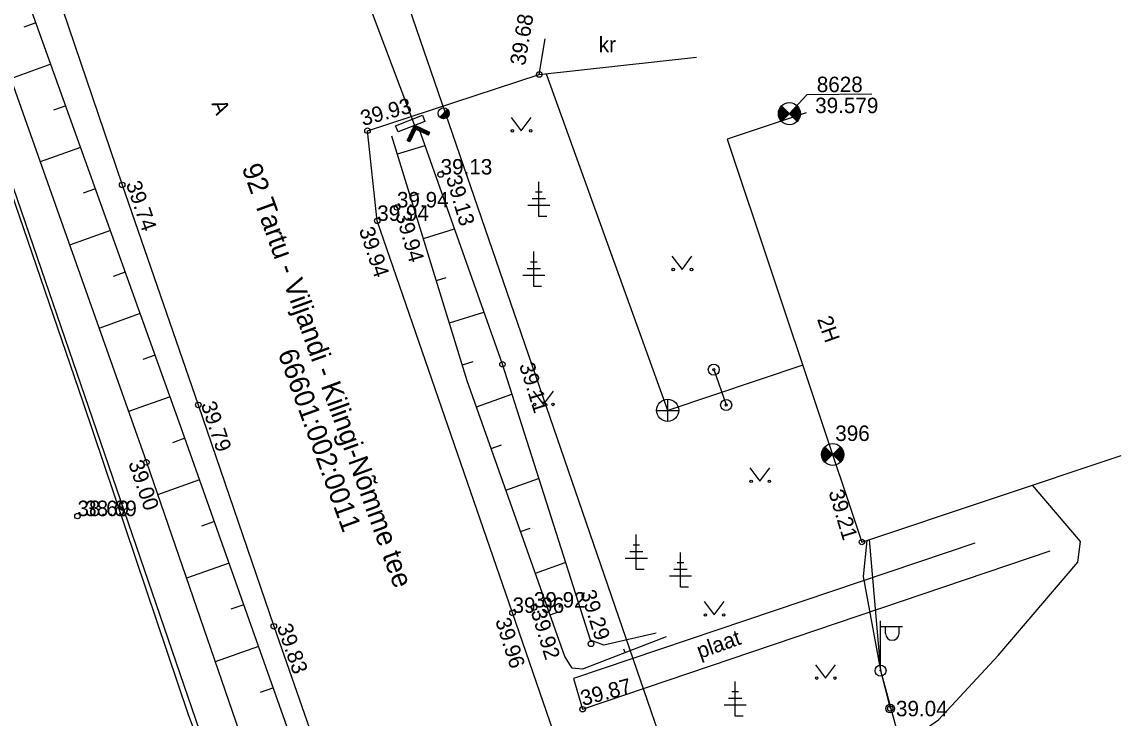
# Model space of a CAD drawing. Extents: x 627548 to 628052, y 6467984 to 6468802.
# Drawn here: x 627961.02 to 628010.83, y 6468057.42 to 6468088.95 of the extents above; entities that cross this region are included whole.
import ezdxf

# ---------------------------------------------------------------- set-up
doc = ezdxf.new("R2010")
doc.units = 0
for name, color, linetype in [('ALUSVORK', 7, 'Continuous'), ('HALJASTUS', 7, 'Continuous'), ('HOONE', 7, 'Continuous'), ('KKAEV', 7, 'Continuous'), ('KORGUS-EH2000', 7, 'Continuous'), ('KTRASS', 7, 'Continuous'), ('LIIKLUS', 7, 'Continuous'), ('MOOTKORG-EH2000', 7, 'Continuous'), ('MOOTMPUNKT', 7, 'Continuous'), ('MPKAABEL', 7, 'Continuous'), ('MPOHULIIN', 7, 'Continuous'), ('PIIR', 7, 'Continuous'), ('POST', 7, 'Continuous'), ('PUU', 7, 'Continuous'), ('RELJEEF', 7, 'Continuous'), ('SITRASS', 7, 'Continuous'), ('TEE', 7, 'Continuous'), ('TRUUP', 7, 'Continuous')]:
    doc.layers.add(name, color=color, linetype=linetype)

msp = doc.modelspace()

# ---------------------------------------------------------------- linework, layer by layer
at = {"layer": 'ALUSVORK'}
for p, q in [((627995.446, 6468085.154), (627996.154, 6468084.446)), ((627995.446, 6468084.446), (627996.154, 6468085.154)), ((627995.446, 6468085.154), (627995.446, 6468085.154)), ((627995.446, 6468085.154), (627995.446, 6468085.154)), ((627996.154, 6468085.154), (627996.154, 6468085.154)), ((627995.446, 6468084.446), (627995.446, 6468084.446)), ((627996.154, 6468084.446), (627996.154, 6468084.446)), ((627996.154, 6468084.446), (627996.154, 6468084.446)), ((627997.404, 6468069.713), (627998.111, 6468069.006)), ((627997.404, 6468069.006), (627998.111, 6468069.713)), ((627997.404, 6468069.713), (627997.404, 6468069.713)), ((627997.404, 6468069.713), (627997.404, 6468069.713)), ((627998.111, 6468069.713), (627998.111, 6468069.713)), ((627997.404, 6468069.006), (627997.404, 6468069.006)), ((627998.111, 6468069.006), (627998.111, 6468069.006)), ((627998.111, 6468069.006), (627998.111, 6468069.006))]:
    msp.add_line(p, q, dxfattribs=at)
msp.add_lwpolyline([(627999.534, 6468085.677), (627996.592, 6468085.654), (627995.8, 6468084.8)], dxfattribs=at)
for centre in [(627995.8, 6468084.8), (627997.757, 6468069.359)]:
    msp.add_circle(centre, 0.5, dxfattribs=at)
for centre, radius, start, end in [((627995.8, 6468084.8), 0.475, 135.0005, 224.9995), ((627995.8, 6468084.8), 0.45, 135.0005, 224.9995), ((627995.8, 6468084.8), 0.425, 135.0005, 224.9995), ((627995.8, 6468084.8), 0.4, 135.0005, 224.9995), ((627995.8, 6468084.8), 0.375, 135.0005, 224.9995), ((627995.8, 6468084.8), 0.35, 135.0005, 224.9995), ((627995.8, 6468084.8), 0.325, 135.0005, 224.9995), ((627995.8, 6468084.8), 0.3, 135.0005, 224.9995), ((627995.8, 6468084.8), 0.275, 135.0005, 224.9995), ((627995.8, 6468084.8), 0.275, 315.0005, 44.9995), ((627995.8, 6468084.8), 0.3, 315.0005, 44.9995), ((627995.8, 6468084.8), 0.325, 315.0005, 44.9995), ((627995.8, 6468084.8), 0.35, 315.0005, 44.9995), ((627995.8, 6468084.8), 0.375, 315.0005, 44.9995), ((627995.8, 6468084.8), 0.4, 315.0005, 44.9995), ((627995.8, 6468084.8), 0.425, 315.0005, 44.9995), ((627995.8, 6468084.8), 0.45, 315.0005, 44.9995), ((627995.8, 6468084.8), 0.475, 315.0005, 44.9995), ((627995.8, 6468084.8), 0.25, 135.0005, 224.9995), ((627995.8, 6468084.8), 0.225, 135.0005, 224.9995), ((627995.8, 6468084.8), 0.2, 135.0005, 224.9995), ((627995.8, 6468084.8), 0.175, 135.0005, 224.9995), ((627995.8, 6468084.8), 0.15, 135.0005, 224.9995), ((627995.8, 6468084.8), 0.125, 135.0005, 224.9995), ((627995.8, 6468084.8), 0.1, 135.0005, 224.9995), ((627995.8, 6468084.8), 0.075, 135.0005, 224.9995), ((627995.8, 6468084.8), 0.05, 135.0005, 224.9995), ((627995.8, 6468084.8), 0.025, 135.0005, 224.9995), ((627995.8, 6468084.8), 0.025, 315.0005, 44.9995), ((627995.8, 6468084.8), 0.05, 315.0005, 44.9995), ((627995.8, 6468084.8), 0.075, 315.0005, 44.9995), ((627995.8, 6468084.8), 0.1, 315.0005, 44.9995), ((627995.8, 6468084.8), 0.125, 315.0005, 44.9995), ((627995.8, 6468084.8), 0.15, 315.0005, 44.9995), ((627995.8, 6468084.8), 0.175, 315.0005, 44.9995), ((627995.8, 6468084.8), 0.2, 315.0005, 44.9995), ((627995.8, 6468084.8), 0.225, 315.0005, 44.9995), ((627995.8, 6468084.8), 0.25, 315.0005, 44.9995), ((627997.757, 6468069.359), 0.475, 135.0005, 224.9995), ((627997.757, 6468069.359), 0.45, 135.0005, 224.9995), ((627997.757, 6468069.359), 0.425, 135.0005, 224.9995), ((627997.757, 6468069.359), 0.4, 135.0005, 224.9995), ((627997.757, 6468069.359), 0.375, 135.0005, 224.9995), ((627997.757, 6468069.359), 0.35, 135.0005, 224.9995), ((627997.757, 6468069.359), 0.325, 135.0005, 224.9995), ((627997.757, 6468069.359), 0.3, 135.0005, 224.9995), ((627997.757, 6468069.359), 0.275, 135.0005, 224.9995), ((627997.757, 6468069.359), 0.275, 315.0005, 44.9995), ((627997.757, 6468069.359), 0.3, 315.0005, 44.9995), ((627997.757, 6468069.359), 0.325, 315.0005, 44.9995), ((627997.757, 6468069.359), 0.35, 315.0005, 44.9995), ((627997.757, 6468069.359), 0.375, 315.0005, 44.9995), ((627997.757, 6468069.359), 0.4, 315.0005, 44.9995), ((627997.757, 6468069.359), 0.425, 315.0005, 44.9995), ((627997.757, 6468069.359), 0.45, 315.0005, 44.9995), ((627997.757, 6468069.359), 0.475, 315.0005, 44.9995), ((627997.757, 6468069.359), 0.25, 135.0005, 224.9995), ((627997.757, 6468069.359), 0.225, 135.0005, 224.9995), ((627997.757, 6468069.359), 0.2, 135.0005, 224.9995), ((627997.757, 6468069.359), 0.175, 135.0005, 224.9995), ((627997.757, 6468069.359), 0.15, 135.0005, 224.9995), ((627997.757, 6468069.359), 0.125, 135.0005, 224.9995), ((627997.757, 6468069.359), 0.1, 135.0005, 224.9995), ((627997.757, 6468069.359), 0.075, 135.0005, 224.9995), ((627997.757, 6468069.359), 0.05, 135.0005, 224.9995), ((627997.757, 6468069.359), 0.025, 135.0005, 224.9995), ((627997.757, 6468069.359), 0.025, 315.0005, 44.9995), ((627997.757, 6468069.359), 0.05, 315.0005, 44.9995), ((627997.757, 6468069.359), 0.075, 315.0005, 44.9995), ((627997.757, 6468069.359), 0.1, 315.0005, 44.9995), ((627997.757, 6468069.359), 0.125, 315.0005, 44.9995), ((627997.757, 6468069.359), 0.15, 315.0005, 44.9995), ((627997.757, 6468069.359), 0.175, 315.0005, 44.9995), ((627997.757, 6468069.359), 0.2, 315.0005, 44.9995), ((627997.757, 6468069.359), 0.225, 315.0005, 44.9995), ((627997.757, 6468069.359), 0.25, 315.0005, 44.9995)]:
    msp.add_arc(centre, radius, start, end, dxfattribs=at)
at = {"layer": 'HALJASTUS'}
for p, q in [((627983.182, 6468084.628), (627983.645, 6468084.021)), ((627983.645, 6468084.021), (627984.091, 6468084.628)), ((627990.47, 6468078.346), (627990.933, 6468077.739)), ((627990.933, 6468077.739), (627991.379, 6468078.346)), ((627984.191, 6468072.231), (627984.655, 6468071.625)), ((627984.655, 6468071.625), (627985.1, 6468072.231)), ((627994.002, 6468068.754), (627994.465, 6468068.147)), ((627994.465, 6468068.147), (627994.911, 6468068.754)), ((627991.928, 6468062.696), (627992.391, 6468062.089)), ((627992.391, 6468062.089), (627992.837, 6468062.696)), ((627996.973, 6468059.835), (627997.437, 6468059.228)), ((627997.437, 6468059.228), (627997.882, 6468059.835))]:
    msp.add_line(p, q, dxfattribs=at)
for centre in [(627983.244, 6468084.021), (627984.073, 6468084.021), (627990.532, 6468077.739), (627991.361, 6468077.739), (627984.254, 6468071.625), (627985.082, 6468071.625), (627994.064, 6468068.147), (627994.893, 6468068.147), (627991.99, 6468062.089), (627992.819, 6468062.089), (627997.036, 6468059.228), (627997.864, 6468059.228)]:
    msp.add_circle(centre, 0.055, dxfattribs=at)
at = {"layer": 'HOONE'}
msp.add_lwpolyline([(627996.552, 6468084.834), (627992.984, 6468083.642), (627999.083, 6468065.393), (628010.826, 6468069.318)], dxfattribs=at)
at = {"layer": 'KKAEV'}
for p, q in [((627990.282, 6468070.859), (627990.282, 6468071.859)), ((627989.782, 6468071.359), (627990.782, 6468071.359))]:
    msp.add_line(p, q, dxfattribs=at)
msp.add_circle((627990.282, 6468071.359), 0.5, dxfattribs=at)
at = {"layer": 'KORGUS-EH2000'}
for centre in [(627984.465, 6468086.573), (627976.679, 6468084.026), (627965.56, 6468081.571), (627982.794, 6468073.444), (627969.012, 6468071.605), (627966.658, 6468069.004), (627999.083, 6468065.393), (627972.432, 6468061.577), (627986.81, 6468060.78), (627986.425, 6468057.82), (628000.367, 6468057.85)]:
    msp.add_circle(centre, 0.125, dxfattribs=at)
at = {"layer": 'KTRASS'}
for points in [[(627990.282, 6468071.359), (627984.783, 6468086.585)], [(627996.405, 6468073.406), (627990.282, 6468071.359)]]:
    msp.add_lwpolyline(points, dxfattribs=at)
at = {"layer": 'LIIKLUS'}
msp.add_lwpolyline([(627992.371, 6468073.203), (627992.932, 6468071.603)], dxfattribs=at)
for centre, radius in [((627992.371, 6468073.203), 0.25), ((627992.371, 6468073.203), 0.05), ((627992.932, 6468071.603), 0.25), ((627992.932, 6468071.603), 0.05)]:
    msp.add_circle(centre, radius, dxfattribs=at)
at = {"layer": 'MOOTMPUNKT'}
for centre in [(627979.991, 6468082.043), (627978.012, 6468080.551), (627977.119, 6468079.943), (627963.533, 6468066.568), (627983.251, 6468062.182), (627984.22, 6468062.427)]:
    msp.add_circle(centre, 0.125, dxfattribs=at)
at = {"layer": 'MPKAABEL'}
msp.add_lwpolyline([(627999.313, 6468065.47), (627999.141, 6468063.833), (627999.927, 6468059.569)], dxfattribs=at)
at = {"layer": 'MPOHULIIN'}
for points in [[(627999.41, 6468065.503), (627999.927, 6468059.569)], [(627999.927, 6468059.569), (628001.908, 6468052.307)]]:
    msp.add_lwpolyline(points, dxfattribs=at)
at = {"layer": 'PIIR'}
for p, q in [((627946.33, 6468123.08), (627981.87, 6468019.49)), ((627976.14, 6468096.65), (628002.94, 6468018.71))]:
    msp.add_line(p, q, dxfattribs=at)
at = {"layer": 'POST'}
for p, q in [((627979.95, 6468084.642), (627980.304, 6468084.995)), ((627999.927, 6468059.819), (627999.927, 6468061.819)), ((627999.927, 6468061.569), (628000.927, 6468061.569)), ((628000.154, 6468061.248), (628000.154, 6468061.569)), ((628000.766, 6468061.248), (628000.766, 6468061.569))]:
    msp.add_line(p, q, dxfattribs=at)
msp.add_lwpolyline([(627999.927, 6468059.569), (628000.367, 6468057.85)], dxfattribs=at)
for centre, radius in [((627980.127, 6468084.818), 0.25), ((627999.927, 6468059.569), 0.25), ((627999.927, 6468059.569), 0.0234), ((628000.367, 6468057.85), 0.2)]:
    msp.add_circle(centre, radius, dxfattribs=at)
for centre, radius, start, end in [((627980.127, 6468084.818), 0.225, 224.8541, 45.0356), ((627980.127, 6468084.818), 0.2, 224.8427, 45.047), ((627980.127, 6468084.818), 0.175, 224.8281, 45.0616), ((627980.127, 6468084.818), 0.15, 224.8087, 45.081), ((627980.127, 6468084.818), 0.125, 224.7814, 45.1083), ((627980.127, 6468084.818), 0.1, 224.7406, 45.1491), ((627980.127, 6468084.818), 0.075, 224.6725, 45.2172), ((627980.127, 6468084.818), 0.05, 224.5363, 45.3534), ((627980.127, 6468084.818), 0.025, 224.1278, 45.7619), ((628000.46, 6468061.248), 0.306, 180, 0)]:
    msp.add_arc(centre, radius, start, end, dxfattribs=at)
at = {"layer": 'PUU'}
for p, q in [((627984.44, 6468080.14), (627984.44, 6468081.715)), ((627984.59, 6468081.24), (627984.29, 6468081.24)), ((627984.94, 6468080.64), (627983.94, 6468080.64)), ((627984.74, 6468080.94), (627984.14, 6468080.94)), ((627984.8, 6468080.14), (627984.44, 6468080.14)), ((627984.211, 6468076.973), (627984.211, 6468078.548)), ((627984.361, 6468078.073), (627984.061, 6468078.073)), ((627984.511, 6468077.773), (627983.911, 6468077.773)), ((627984.711, 6468077.473), (627983.711, 6468077.473)), ((627984.571, 6468076.973), (627984.211, 6468076.973)), ((627988.861, 6468064.154), (627988.861, 6468065.729)), ((627989.011, 6468065.254), (627988.711, 6468065.254)), ((627989.361, 6468064.654), (627988.361, 6468064.654)), ((627989.161, 6468064.954), (627988.561, 6468064.954)), ((627990.859, 6468063.349), (627990.859, 6468064.924)), ((627989.221, 6468064.154), (627988.861, 6468064.154)), ((627991.159, 6468064.149), (627990.559, 6468064.149)), ((627991.009, 6468064.449), (627990.709, 6468064.449)), ((627991.359, 6468063.849), (627990.359, 6468063.849)), ((627991.219, 6468063.349), (627990.859, 6468063.349)), ((627993.486, 6468058.607), (627993.186, 6468058.607)), ((627993.336, 6468057.507), (627993.336, 6468059.082)), ((627993.636, 6468058.307), (627993.036, 6468058.307)), ((627993.836, 6468058.007), (627992.836, 6468058.007)), ((627993.696, 6468057.507), (627993.336, 6468057.507))]:
    msp.add_line(p, q, dxfattribs=at)
at = {"layer": 'RELJEEF'}
for p, q in [((627961.651, 6468088.919), (627961.105, 6468088.723)), ((627962.326, 6468087.036), (627960.502, 6468086.381)), ((627963.002, 6468085.154), (627962.452, 6468084.956)), ((627963.677, 6468083.271), (627961.837, 6468082.611)), ((627978.034, 6468082.972), (627979.285, 6468083.357)), ((627964.353, 6468081.389), (627963.798, 6468081.19)), ((627978.623, 6468081.061), (627979.022, 6468081.184)), ((627965.028, 6468079.506), (627963.173, 6468078.841)), ((627979.211, 6468079.15), (627980.621, 6468079.583)), ((627965.703, 6468077.624), (627965.145, 6468077.423)), ((627979.799, 6468077.238), (627980.246, 6468077.376)), ((627966.379, 6468075.741), (627964.509, 6468075.07)), ((627980.388, 6468075.327), (627981.957, 6468075.81)), ((627967.054, 6468073.859), (627966.491, 6468073.657)), ((627980.976, 6468073.415), (627981.471, 6468073.567)), ((627981.614, 6468071.52), (627983.223, 6468072.09)), ((627967.73, 6468071.976), (627965.845, 6468071.3)), ((627968.403, 6468070.093), (627967.835, 6468069.892)), ((627982.282, 6468069.635), (627982.746, 6468069.799)), ((627969.071, 6468068.208), (627967.166, 6468067.533)), ((627982.949, 6468067.749), (627984.433, 6468068.275)), ((627969.74, 6468066.323), (627969.163, 6468066.119)), ((627983.617, 6468065.864), (627984.043, 6468066.015)), ((627970.408, 6468064.438), (627968.47, 6468063.751)), ((627984.285, 6468063.979), (627985.643, 6468064.46)), ((627971.076, 6468062.553), (627970.49, 6468062.345)), ((627984.952, 6468062.094), (627985.341, 6468062.231)), ((627971.744, 6468060.667), (627969.774, 6468059.97)), ((627988.348, 6468060.382), (627988.288, 6468060.537)), ((627972.412, 6468058.782), (627971.816, 6468058.571))]:
    msp.add_line(p, q, dxfattribs=at)
for points in [[(627978.291, 6468008.882), (627983.457, 6468013.678), (627984.21, 6468021.024), (627979.575, 6468037.02), (627973.979, 6468054.36), (627968.222, 6468070.605), (627961.466, 6468089.433), (627957.405, 6468099.776), (627954.697, 6468099.952), (627954.601, 6468100.77), (627956.677, 6468103.285), (627952.114, 6468117.091), (627946.482, 6468133.262), (627941.383, 6468147.782), (627936.221, 6468162.714), (627931.414, 6468176.011), (627926.765, 6468189.068), (627921.448, 6468202.325), (627917.805, 6468212.302), (627916.173, 6468214.408), (627912.962, 6468214.481), (627910.459, 6468214.182)], [(627910.966, 6468212.647), (627913.157, 6468213.418), (627915.522, 6468212.557), (627919.56, 6468201.376), (627924.571, 6468188.424), (627929.207, 6468175.576), (627934.909, 6468161.365), (627939.161, 6468147.561), (627944.576, 6468131.872), (627949.813, 6468116.897), (627954.804, 6468102.831), (627953.147, 6468101.408), (627953.982, 6468098.417), (627956.488, 6468098.118), (627959.583, 6468088.974), (627966.658, 6468069.004), (627971.68, 6468054.444), (627977.14, 6468035.885), (627981.189, 6468020.389), (627981.639, 6468013.545), (627978.211, 6468009.476)], [(627986.79, 6468060.949), (627982.794, 6468073.444), (627979.015, 6468084.119)], [(627985.952, 6468059.681), (627985.62, 6468060.208), (627981.197, 6468072.698), (627977.786, 6468083.778)], [(627990.213, 6468061.104), (627986.429, 6468059.64), (627985.952, 6468059.681)], [(627989.763, 6468061.265), (627987.382, 6468060.722), (627986.79, 6468060.949)]]:
    msp.add_lwpolyline(points, dxfattribs=at)
at = {"layer": 'SITRASS'}
for points in [[(627969.796, 6467996.723), (627973.191, 6467998.006), (627976.323, 6467999.384), (627976.439, 6468000.299), (627974.452, 6468004.589), (627974.615, 6468005.444), (627975.744, 6468006.43), (627979.437, 6468008.95), (627982.801, 6468012.806), (627983.762, 6468016.772), (627983.396, 6468018.821), (627982.465, 6468019.728), (627980.449, 6468024.262), (627973.928, 6468043.378), (627968.573, 6468057.558), (627963.8, 6468071.726), (627958.775, 6468086.331), (627947.216, 6468119.583), (627940.944, 6468137.544)], [(627972.74, 6468046.714), (627973.751, 6468047.209), (627976.725, 6468048.008), (627982.226, 6468049.69), (627988.02, 6468051.44), (627991.483, 6468052.786), (628001.207, 6468056.403), (628002.562, 6468057.339), (628005.253, 6468060.26), (628008.875, 6468064.486), (628008.99, 6468065.414), (628006.811, 6468067.976)]]:
    msp.add_lwpolyline(points, dxfattribs=at)
at = {"layer": 'TEE'}
for points in [[(627948.73, 6468130.073), (627952.157, 6468120.49), (627955.55, 6468110.522), (627958.987, 6468100.641), (627962.318, 6468091.154), (627965.56, 6468081.571), (627969.012, 6468071.605), (627972.432, 6468061.577), (627975.777, 6468052.007), (627979.213, 6468042.181), (627982.519, 6468032.549), (627985.763, 6468023.005), (627987.717, 6468016.784), (627987.108, 6468013.905), (627990.1, 6468007.105), (627992.636, 6468000.403), (627994.498, 6467998.047), (627996.95, 6467991.167)], [(628006.43, 6467993.97), (628003.022, 6468005.387), (628001.133, 6468010.151), (627997.263, 6468021.078), (627994.391, 6468029.349), (627993.344, 6468032.587), (627988.048, 6468048.243), (627983.251, 6468062.182), (627977.119, 6468079.943), (627976.679, 6468084.026), (627984.465, 6468086.573), (627984.734, 6468088.185)], [(627984.465, 6468086.573), (627991.581, 6468087.351)], [(628004.202, 6468065.337), (627986.011, 6468059.206), (627986.425, 6468057.82), (628007.617, 6468064.994)]]:
    msp.add_lwpolyline(points, dxfattribs=at)
at = {"layer": 'TRUUP'}
for p, q in [((627978.802, 6468084.284), (627978.469, 6468083.581)), ((627978.836, 6468084.189), (627978.533, 6468083.55)), ((627978.87, 6468084.094), (627978.598, 6468083.52)), ((627978.768, 6468083.879), (627978.67, 6468084.005)), ((627978.78, 6468083.904), (627978.682, 6468084.03)), ((627978.792, 6468083.93), (627978.694, 6468084.055)), ((627978.804, 6468083.955), (627978.706, 6468084.081)), ((627978.816, 6468083.98), (627978.718, 6468084.106)), ((627978.828, 6468084.006), (627978.73, 6468084.131)), ((627978.84, 6468084.031), (627978.742, 6468084.157)), ((627978.852, 6468084.056), (627978.754, 6468084.182)), ((627978.864, 6468084.081), (627978.766, 6468084.207)), ((627978.894, 6468084.083), (627978.778, 6468084.232)), ((627978.944, 6468084.059), (627978.79, 6468084.258)), ((627979.505, 6468083.951), (627978.802, 6468084.284)), ((627978.994, 6468084.035), (627978.802, 6468084.283)), ((627979.475, 6468083.887), (627978.836, 6468084.189)), ((627979.045, 6468084.012), (627978.85, 6468084.261)), ((627979.445, 6468083.822), (627978.87, 6468084.094)), ((627979.095, 6468083.988), (627978.901, 6468084.237)), ((627979.145, 6468083.964), (627978.951, 6468084.214)), ((627979.195, 6468083.94), (627979.001, 6468084.19)), ((627979.246, 6468083.917), (627979.051, 6468084.166)), ((627979.296, 6468083.893), (627979.101, 6468084.142)), ((627979.346, 6468083.869), (627979.152, 6468084.119)), ((627979.396, 6468083.845), (627979.202, 6468084.095)), ((627979.445, 6468083.823), (627979.252, 6468084.071)), ((627979.457, 6468083.848), (627979.302, 6468084.047)), ((627979.469, 6468083.874), (627979.352, 6468084.023)), ((627979.481, 6468083.899), (627979.403, 6468084)), ((627978.598, 6468083.52), (627978.469, 6468083.581)), ((627978.507, 6468083.563), (627978.478, 6468083.6)), ((627978.557, 6468083.539), (627978.49, 6468083.625)), ((627978.6, 6468083.525), (627978.502, 6468083.651)), ((627978.612, 6468083.55), (627978.514, 6468083.676)), ((627978.624, 6468083.575), (627978.526, 6468083.701)), ((627978.636, 6468083.601), (627978.538, 6468083.726)), ((627978.648, 6468083.626), (627978.55, 6468083.752)), ((627978.66, 6468083.651), (627978.562, 6468083.777)), ((627978.672, 6468083.677), (627978.574, 6468083.802)), ((627978.684, 6468083.702), (627978.586, 6468083.828)), ((627978.696, 6468083.727), (627978.598, 6468083.853)), ((627978.708, 6468083.753), (627978.61, 6468083.878)), ((627978.72, 6468083.778), (627978.622, 6468083.904)), ((627978.732, 6468083.803), (627978.634, 6468083.929)), ((627978.744, 6468083.828), (627978.646, 6468083.954)), ((627978.756, 6468083.854), (627978.658, 6468083.979)), ((627979.445, 6468083.822), (627979.505, 6468083.951)), ((627979.493, 6468083.924), (627979.453, 6468083.976))]:
    msp.add_line(p, q, dxfattribs=at)
for points in [[(627976.412, 6468090.651), (627978.836, 6468084.189)], [(627977.954, 6468084.248), (627979.175, 6468084.726), (627979.283, 6468084.451), (627978.062, 6468083.972), (627977.954, 6468084.248)]]:
    msp.add_lwpolyline(points, dxfattribs=at)

# ---------------------------------------------------------------- texts
at = {"layer": 'ALUSVORK'}
for s, p in [('8628', (627997.039, 6468085.774)), ('39.579', (627996.966, 6468084.823)), ('396', (627997.877, 6468069.971))]:
    msp.add_text(s, height=0.7, dxfattribs=at).set_placement(p)
at = {"layer": 'HOONE'}
msp.add_text('2H', height=0.7, rotation=289.4959, dxfattribs=at).set_placement((627997.044, 6468075.493))
at = {"layer": 'KORGUS-EH2000'}
for s, rotation, p in [(' 39.68', 80.5262, (627983.775, 6468086.689)), (' 39.93', 15.2727, (627976.219, 6468084.167)), ('39.13', 286.3051, (627980.229, 6468081.901)), (' 39.74', 289.1049, (627965.637, 6468081.865)), ('39.94', 286.3115, (627977.933, 6468080.251)), ('39.94', 288.2899, (627976.283, 6468079.541)), (' 39.11', 287.5948, (627983.461, 6468073.656)), (' 39.79', 288.8317, (627969.032, 6468071.877)), (' 39.00', 289.0302, (627965.743, 6468069.216)), (' 39.21', 286.7963, (627997.486, 6468067.911)), (' 39.29', 287.5948, (627986.237, 6468063.356)), ('39.92', 286.9911, (627984.069, 6468062.247)), (' 39.83', 289.266, (627972.475, 6468061.808)), ('39.96', 287.7349, (627982.458, 6468061.839)), (' 39.87', 14.8308, (627986.186, 6468057.895))]:
    msp.add_text(s, height=0.7, rotation=rotation, dxfattribs=at).set_placement(p)
for s, p in [('38.69', (627963.883, 6468066.568)), (' 39.04', (628000.367, 6468057.5))]:
    msp.add_text(s, height=0.7, dxfattribs=at).set_placement(p)
at = {"layer": 'MOOTKORG-EH2000'}
for s, p in [('39.13', (627979.991, 6468082.043)), ('39.94', (627978.012, 6468080.551)), ('39.94', (627977.119, 6468079.943)), ('38.69', (627963.533, 6468066.568)), ('39.92', (627984.22, 6468062.427)), ('39.96', (627983.251, 6468062.182))]:
    msp.add_text(s, height=0.7, dxfattribs=at).set_placement(p)
at = {"layer": 'PIIR'}
for s, p in [('92 Tartu - Viljandi - Kilingi-Nõmme tee', (627970.97, 6468082.348)), ('66601:002:0011', (627972.604, 6468073.951))]:
    msp.add_text(s, height=0.9, rotation=289.9584, dxfattribs=at).set_placement(p)
at = {"layer": 'TEE'}
msp.add_text('kr', height=0.7, dxfattribs=at).set_placement((627987.159, 6468087.584))
for s, rotation, p in [('A', 292.1156, (627969.594, 6468085.259)), ('plaat', 19.4459, (627991.745, 6468060.101))]:
    msp.add_text(s, height=0.7, rotation=rotation, dxfattribs=at).set_placement(p)

doc.saveas('drawing.dxf')
